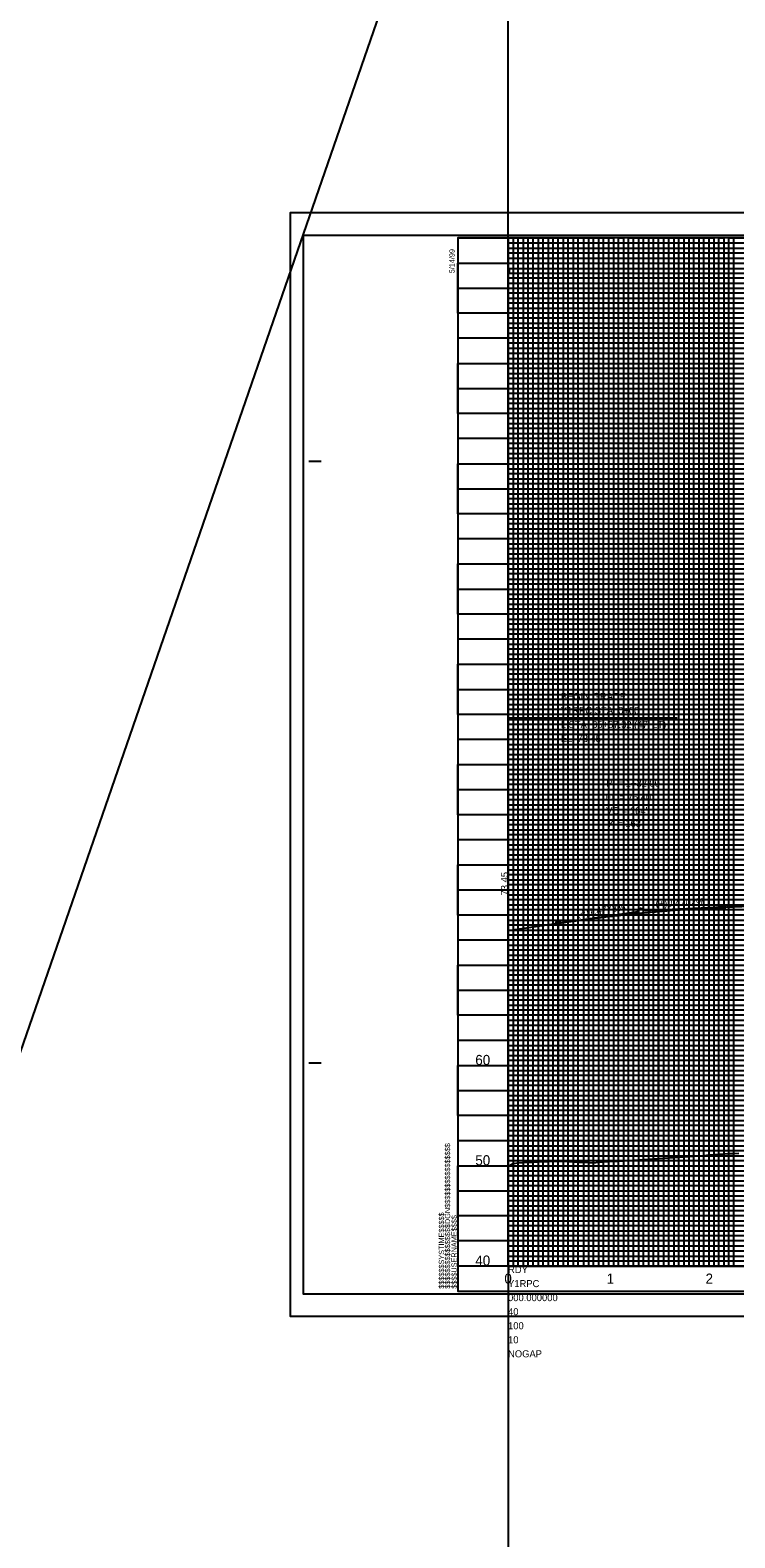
# Model space of a CAD drawing. Extents: x 2345490 to 2445302, y 465165 to 573888.
# Drawn here: x 2410419 to 2411121, y 508449 to 509953 of the extents above; entities that cross this region are included whole.
import ezdxf

# ---------------------------------------------------------------- set-up
doc = ezdxf.new("R2010")
doc.units = 0
for name, color, linetype in [('Old_Level_1', 7, 'Continuous'), ('Old_Level_18', 7, 'Continuous'), ('Old_Level_2', 7, 'Continuous'), ('Old_Level_40', 7, 'Continuous'), ('Old_Level_41', 7, 'Continuous'), ('Old_Level_42', 7, 'Continuous'), ('Old_Level_43', 7, 'Continuous'), ('Old_Level_50', 7, 'Continuous'), ('Old_Level_51', 7, 'Continuous'), ('Old_Level_52', 7, 'Continuous'), ('Old_Level_63', 7, 'Continuous')]:
    doc.layers.add(name, color=color, linetype=linetype)

msp = doc.modelspace()

# ---------------------------------------------------------------- linework, layer by layer
at = {"layer": 'Old_Level_1'}
msp.add_lwpolyline([(2410895.325, 508819.65725), (2410900.325, 508822.7005), (2410905.325, 508823.16675), (2410910.325, 508823.63275), (2410915.325, 508823.853), (2410920.325, 508824.06825), (2410925.325, 508824.28325), (2410930.325, 508824.49775), (2410935.325, 508824.71225), (2410940.325, 508824.87375), (2410945.325, 508824.87125), (2410950.325, 508824.8685), (2410955.325, 508824.62775), (2410960.325, 508824.3675), (2410965.325, 508824.10725), (2410970.325, 508823.847), (2410975.325, 508823.5865), (2410980.325, 508823.483), (2410985.325, 508823.8715), (2410990.325, 508824.25975), (2410995.325, 508824.56), (2411000.325, 508824.831), (2411005.325, 508825.10225), (2411010.325, 508825.37375), (2411015.325, 508825.64525), (2411020.325, 508825.92725), (2411025.325, 508826.2425), (2411030.325, 508826.55775), (2411035.325, 508826.87925), (2411040.325, 508827.21125), (2411045.325, 508827.5435), (2411050.325, 508827.87575), (2411055.325, 508828.20825), (2411060.325, 508828.54275), (2411065.325, 508828.88375), (2411070.325, 508829.225), (2411075.325, 508829.56625), (2411080.325, 508829.94425), (2411085.325, 508830.3465), (2411090.325, 508830.7485), (2411095.325, 508831.15025), (2411100.325, 508831.53675), (2411105.325, 508831.8515), (2411110.325, 508832.16575), (2411115.325, 508832.4795), (2411120.325, 508832.793), (2411125.325, 508833.0915)], dxfattribs=at)
at = {"layer": 'Old_Level_18'}
msp.add_line((2410845.325, 508695.412), (2410845.325, 508695.412), dxfattribs=at)
msp.add_line((2410845.325, 508695.412), (2410845.325, 508695.412), dxfattribs=at)
msp.add_lwpolyline([(2412345.325, 509745.412), (2410845.325, 509745.412), (2410845.325, 508695.412), (2412345.325, 508695.412)], close=True, dxfattribs=at)
at = {"layer": 'Old_Level_2'}
for p, q in [((2406888.2485, 498751.813), (2414623.19775, 521117.51825)), ((2410895.325, 509266.712), (2410895.325, 509047.812)), ((2411063.7915, 509266.712), (2410895.325, 509266.712)), ((2411109.325, 509078.268), (2411030.072, 509074.54125)), ((2411109.325, 509078.268), (2411192.57825, 509082.183)), ((2410895.325, 509054.912), (2410945.325, 509062.2985)), ((2410945.325, 509062.2985), (2411024.60475, 509074.01025))]:
    msp.add_line(p, q, dxfattribs=at)
for centre, radius in [((2411027.325, 509074.412), 2.75), ((2411109.325, 509078.268), 2.25), ((2410945.325, 509062.2985), 2.25)]:
    msp.add_circle(centre, radius, dxfattribs=at)
for points in [[(2410945.325, 509062.2985), (2410948.605, 509062.77975), (2410951.885, 509063.25425), (2410955.165, 509063.7225), (2410958.445, 509064.18375), (2410961.725, 509064.63875), (2410965.005, 509065.08675), (2410968.285, 509065.5285), (2410971.565, 509065.9635), (2410974.845, 509066.39175), (2410978.125, 509066.81375), (2410981.405, 509067.22875), (2410984.685, 509067.6375), (2410987.965, 509068.03925), (2410991.245, 509068.43475), (2410994.525, 509068.8235), (2410997.805, 509069.20575), (2411001.085, 509069.58125), (2411004.365, 509069.95), (2411007.645, 509070.3125), (2411010.925, 509070.66825), (2411014.205, 509071.01725), (2411017.485, 509071.35975), (2411020.765, 509071.69575), (2411024.045, 509072.025), (2411027.325, 509072.34775), (2411030.605, 509072.66375), (2411033.885, 509072.97325), (2411037.165, 509073.27625), (2411040.445, 509073.5725), (2411043.725, 509073.862), (2411047.005, 509074.14525), (2411050.285, 509074.4215), (2411053.565, 509074.6915), (2411056.845, 509074.95475), (2411060.125, 509075.21125), (2411063.405, 509075.46125), (2411066.685, 509075.70475), (2411069.965, 509075.9415), (2411073.245, 509076.17175), (2411076.525, 509076.3955), (2411079.805, 509076.6125), (2411083.085, 509076.82275), (2411086.365, 509077.0265), (2411089.645, 509077.22375), (2411092.925, 509077.41425), (2411096.205, 509077.59825), (2411099.485, 509077.77575), (2411102.765, 509077.9465), (2411106.045, 509078.1105), (2411109.325, 509078.268)], [(2411109.325, 509078.268), (2411112.765, 509078.426), (2411116.205, 509078.576), (2411119.645, 509078.7185), (2411123.085, 509078.85325), (2411126.525, 509078.98), (2411129.965, 509079.09925), (2411133.405, 509079.2105), (2411136.845, 509079.31425), (2411140.285, 509079.41), (2411143.725, 509079.49825), (2411147.165, 509079.57875), (2411150.605, 509079.65125), (2411154.045, 509079.71625), (2411157.485, 509079.7735), (2411160.925, 509079.82275), (2411164.365, 509079.8645), (2411167.805, 509079.89825), (2411171.245, 509079.9245), (2411174.685, 509079.943), (2411178.125, 509079.9535), (2411181.565, 509079.9565), (2411185.005, 509079.95175), (2411188.445, 509079.939), (2411191.885, 509079.91875), (2411195.325, 509079.89075), (2411198.765, 509079.855), (2411202.205, 509079.81125), (2411205.645, 509079.76), (2411209.085, 509079.701), (2411212.525, 509079.634), (2411215.965, 509079.5595), (2411219.405, 509079.47725), (2411222.845, 509079.38725), (2411226.285, 509079.28925), (2411229.725, 509079.18375), (2411233.165, 509079.0705), (2411236.605, 509078.9495), (2411240.045, 509078.8205), (2411243.485, 509078.684), (2411246.925, 509078.53975), (2411250.365, 509078.38775), (2411253.805, 509078.228), (2411257.245, 509078.06025), (2411260.685, 509077.885), (2411264.125, 509077.702), (2411267.565, 509077.51125), (2411271.005, 509077.31275), (2411274.445, 509077.10625), (2411277.885, 509076.89225), (2411281.325, 509076.6705)]]:
    msp.add_spline(points, degree=3, dxfattribs=at)
at = {"layer": 'Old_Level_40'}
msp.add_line((2410845.325, 508695.412), (2410845.325, 508695.412), dxfattribs=at)
msp.add_line((2410845.325, 508695.412), (2410845.325, 508695.412), dxfattribs=at)
msp.add_line((2410845.325, 508695.412), (2410845.325, 508695.412), dxfattribs=at)
msp.add_line((2410845.325, 508695.412), (2410845.325, 508695.412), dxfattribs=at)
at = {"layer": 'Old_Level_41'}
for p, q in [((2410696.825, 509522.912), (2410709.325, 509522.912)), ((2410696.825, 508922.912), (2410709.325, 508922.912)), ((2412345.325, 508720.412), (2410845.325, 508720.412))]:
    msp.add_line(p, q, dxfattribs=at)
for points in [[(2410845.325, 509745.412), (2410895.325, 509745.412), (2410895.325, 508720.412), (2410945.325, 508720.412), (2410945.325, 509745.412), (2410995.325, 509745.412), (2410995.325, 508720.412), (2411045.325, 508720.412), (2411045.325, 509745.412), (2411095.325, 509745.412), (2411095.325, 508720.412), (2411145.325, 508720.412)], [(2410920.325, 508720.412), (2410920.325, 509745.412), (2410970.325, 509745.412), (2410970.325, 508720.412), (2411020.325, 508720.412), (2411020.325, 509745.412), (2411070.325, 509745.412), (2411070.325, 508720.412), (2411120.325, 508720.412), (2411120.325, 509745.412), (2411170.325, 509745.412)], [(2410845.325, 509695.412), (2412145.275, 509695.412)], [(2412145.275, 509645.412), (2410845.325, 509645.412), (2410845.325, 509595.362), (2412345.325, 509595.362)], [(2412345.325, 509570.412), (2410845.325, 509570.412), (2410845.325, 509620.412), (2412145.275, 509620.412)], [(2412345.325, 509545.412), (2410845.325, 509545.412), (2410845.325, 509495.412), (2412345.325, 509495.412)], [(2412345.325, 509470.412), (2410845.325, 509470.412), (2410845.325, 509520.412), (2412345.325, 509520.412)], [(2412345.325, 509445.412), (2410845.325, 509445.412), (2410845.325, 509395.412), (2412345.325, 509395.412)], [(2412345.325, 509345.412), (2410845.325, 509345.412), (2410845.325, 509295.412), (2412345.325, 509295.412)], [(2412345.325, 509245.412), (2410845.325, 509245.412), (2410845.325, 509195.412), (2412345.325, 509195.412)], [(2412345.325, 509145.412), (2410845.325, 509145.412), (2410845.325, 509095.412), (2412345.325, 509095.412)], [(2412345.325, 509070.412), (2410845.325, 509070.412), (2410845.325, 509120.412), (2412345.325, 509120.412)], [(2412345.325, 509045.412), (2410845.325, 509045.412), (2410845.325, 508995.412), (2412345.325, 508995.412)], [(2412345.325, 508970.412), (2410845.325, 508970.412), (2410845.325, 509020.412), (2412345.325, 509020.412)], [(2412345.325, 508945.412), (2410845.325, 508945.412), (2410845.325, 508895.412), (2412345.325, 508895.412)], [(2412345.325, 508845.412), (2410845.325, 508845.412), (2410845.325, 508795.412), (2412345.325, 508795.412)], [(2412345.325, 508770.412), (2410845.325, 508770.412), (2410845.325, 508820.412), (2412345.325, 508820.412)], [(2412345.325, 508745.412), (2410845.325, 508745.412)], [(2410882.825, 508695.412), (2410882.825, 508695.412)]]:
    msp.add_lwpolyline(points, dxfattribs=at)
at = {"layer": 'Old_Level_42'}
for points in [[(2412145.275, 509670.412), (2410845.425, 509670.412), (2410845.425, 509720.362), (2412145.275, 509720.362)], [(2412345.325, 509370.412), (2410845.325, 509370.412), (2410845.325, 509420.412), (2412345.325, 509420.412)], [(2412345.325, 509270.412), (2410845.325, 509270.412), (2410845.325, 509320.412), (2412345.325, 509320.412)], [(2412345.325, 509170.412), (2410845.325, 509170.412), (2410845.325, 509220.412), (2412345.325, 509220.412)], [(2412345.325, 508870.412), (2410845.325, 508870.412), (2410845.325, 508920.412), (2412345.325, 508920.412)]]:
    msp.add_lwpolyline(points, dxfattribs=at)
at = {"layer": 'Old_Level_43'}
for p, q in [((2412295.325, 509565.412), (2410895.325, 509565.412)), ((2410895.325, 509565.412), (2410895.325, 509560.412)), ((2410895.325, 509560.412), (2412295.325, 509560.412)), ((2412295.325, 509540.412), (2410895.325, 509540.412))]:
    msp.add_line(p, q, dxfattribs=at)
for points in [[(2410900.325, 509745.412), (2410905.325, 509745.412), (2410910.325, 509745.412), (2410915.325, 509745.412), (2410925.325, 509745.412), (2410892.275, 509745.412), (2410897.275, 509745.412), (2410855.325, 509745.412), (2410860.325, 509745.412), (2410865.325, 509745.412), (2410875.325, 509745.412), (2410880.325, 509745.412), (2410885.325, 509745.412), (2410890.325, 509745.412), (2410900.325, 509745.412), (2410900.325, 508720.412), (2410905.325, 508720.412), (2410905.325, 509745.412), (2410910.325, 509745.412), (2410910.325, 508720.412), (2410915.325, 508720.412), (2410915.325, 509745.412), (2410925.325, 509745.412), (2410925.325, 508720.412), (2410930.325, 508720.412), (2410930.325, 509745.412), (2410935.325, 509745.412), (2410935.325, 508720.412), (2410940.325, 508720.412), (2410940.325, 509745.412), (2410950.325, 509745.412), (2410950.325, 508720.412), (2410955.325, 508720.412), (2410955.325, 509745.412), (2410960.325, 509745.412), (2410960.325, 508720.412), (2410965.325, 508720.412), (2410965.325, 509745.412), (2410975.325, 509745.412), (2410975.325, 508720.412), (2410980.325, 508720.412), (2410980.325, 509745.412), (2410985.325, 509745.412), (2410985.325, 508720.412), (2410990.325, 508720.412), (2410990.325, 509745.412), (2411000.325, 509745.412), (2411000.325, 508720.412), (2411005.325, 508720.412), (2411005.325, 509745.412), (2411010.325, 509745.412), (2411010.325, 508720.412), (2411015.325, 508720.412), (2411015.325, 509745.412), (2411025.325, 509745.412), (2411025.325, 508720.412), (2411030.325, 508720.412), (2411030.325, 509745.412), (2411035.325, 509745.412), (2411035.325, 508720.412), (2411040.325, 508720.412), (2411040.325, 509745.412), (2411050.325, 509745.412), (2411050.325, 508720.412), (2411055.325, 508720.412), (2411055.325, 509745.412), (2411060.325, 509745.412), (2411060.325, 508720.412)], [(2412145.275, 509740.412), (2410895.325, 509740.412), (2410895.325, 509735.412), (2412145.275, 509735.412)], [(2411060.325, 508720.412), (2411065.325, 508720.412), (2411065.325, 509745.412), (2411075.325, 509745.412), (2411075.325, 508720.412), (2411080.325, 508720.412), (2411080.325, 509745.412), (2411085.325, 509745.412), (2411085.325, 508720.412), (2411090.325, 508720.412), (2411090.325, 509745.412), (2411100.325, 509745.412), (2411100.325, 508720.412), (2411105.325, 508720.412), (2411105.325, 509745.412), (2411105.325, 509745.412), (2411110.325, 509745.412), (2411110.325, 508720.412), (2411115.325, 508720.412), (2411115.325, 509745.412), (2411125.325, 509745.412)], [(2412145.275, 509730.412), (2410895.325, 509730.412), (2410895.325, 509725.412), (2412145.275, 509725.412)], [(2412145.275, 509714.662), (2410896.325, 509714.662), (2410896.325, 509710.412), (2412145.275, 509710.412)], [(2412145.275, 509705.412), (2410895.325, 509705.412), (2410895.325, 509700.412), (2412145.275, 509700.412)], [(2412145.275, 509690.412), (2410895.325, 509690.412), (2410895.325, 509685.412), (2412145.275, 509685.412)], [(2412145.275, 509680.412), (2410895.325, 509680.412), (2410895.325, 509675.412), (2412145.275, 509675.412)], [(2412145.275, 509665.412), (2410895.325, 509665.412), (2410895.325, 509660.412), (2412145.275, 509660.412)], [(2412145.275, 509655.412), (2410895.325, 509655.412), (2410895.325, 509650.412), (2412145.275, 509650.412)], [(2412145.275, 509640.412), (2410895.325, 509640.412), (2410895.325, 509635.412), (2412145.275, 509635.412)], [(2412145.275, 509630.412), (2410895.325, 509630.412), (2410895.325, 509625.412), (2412145.275, 509625.412)], [(2412145.275, 509615.412), (2410895.325, 509615.412), (2410895.325, 509610.412), (2412145.275, 509610.412)], [(2412295.325, 509605.412), (2410895.325, 509605.412), (2410895.325, 509605.412), (2410895.325, 509585.412), (2412295.325, 509585.412)], [(2410895.325, 509600.412), (2412295.325, 509600.412)], [(2412295.325, 509590.412), (2410895.325, 509590.412)], [(2412295.325, 509580.412), (2410895.325, 509580.412), (2410895.325, 509575.412), (2412295.325, 509575.412)], [(2412295.325, 509555.412), (2410895.325, 509555.412), (2410895.325, 509550.412), (2412295.325, 509550.412)], [(2412295.325, 509535.412), (2410895.325, 509535.412), (2410895.325, 509530.412), (2412295.325, 509530.412)], [(2412295.325, 509525.412), (2410895.325, 509525.412)], [(2410895.325, 509515.412), (2412295.325, 509515.412)], [(2412295.325, 509510.412), (2410895.325, 509510.412), (2410895.325, 509505.412), (2412295.325, 509505.412)], [(2412295.325, 509500.412), (2410895.325, 509500.412), (2410895.325, 509490.412), (2412295.325, 509490.412)], [(2412295.325, 509485.412), (2410895.325, 509485.412), (2410895.325, 509480.412), (2412295.325, 509480.412)], [(2412295.325, 509475.412), (2410895.325, 509475.412), (2410895.325, 509465.412), (2412295.325, 509465.412)], [(2412295.325, 509460.412), (2410895.325, 509460.412), (2410895.325, 509455.412), (2412295.325, 509455.412)], [(2412295.325, 509450.412), (2410895.325, 509450.412), (2410895.325, 509440.412), (2412295.325, 509440.412)], [(2412295.325, 509435.412), (2410895.325, 509435.412), (2410895.325, 509430.412), (2412295.325, 509430.412)], [(2412295.325, 509425.412), (2410895.325, 509425.412), (2410895.325, 509415.412), (2412295.325, 509415.412)], [(2412295.325, 509410.412), (2410895.325, 509410.412), (2410895.325, 509405.412), (2412295.325, 509405.412)], [(2412295.325, 509400.412), (2410895.325, 509400.412), (2410895.325, 509390.412), (2412295.325, 509390.412)], [(2412295.325, 509385.412), (2410895.325, 509385.412), (2410895.325, 509380.412), (2412295.325, 509380.412)], [(2412295.325, 509375.412), (2410895.325, 509375.412), (2410895.325, 509365.412), (2412295.325, 509365.412)], [(2412295.325, 509360.412), (2410895.325, 509360.412), (2410895.325, 509355.412), (2412295.325, 509355.412)], [(2412295.325, 509350.412), (2410895.325, 509350.412), (2410895.325, 509340.412), (2412295.325, 509340.412)], [(2412295.325, 509335.412), (2410895.325, 509335.412), (2410895.325, 509330.412), (2412295.325, 509330.412)], [(2412295.325, 509325.412), (2410895.325, 509325.412), (2410895.325, 509315.412), (2412295.325, 509315.412)], [(2412295.325, 509310.412), (2410895.325, 509310.412), (2410895.325, 509305.412), (2412295.325, 509305.412)], [(2412295.325, 509300.412), (2410895.325, 509300.412), (2410895.325, 509290.412), (2412295.325, 509290.412)], [(2412295.325, 509285.412), (2410895.325, 509285.412), (2410895.325, 509280.412), (2412295.325, 509280.412)], [(2412295.325, 509275.412), (2410895.325, 509275.412), (2410895.325, 509265.412), (2412295.325, 509265.412)], [(2412295.325, 509260.412), (2410895.325, 509260.412), (2410895.325, 509255.412), (2412295.325, 509255.412)], [(2412295.325, 509250.412), (2410895.325, 509250.412), (2410895.325, 509240.412), (2412295.325, 509240.412)], [(2412295.325, 509235.412), (2410895.325, 509235.412), (2410895.325, 509230.412), (2412295.325, 509230.412)], [(2412295.325, 509225.412), (2410895.325, 509225.412)], [(2410895.325, 509215.412), (2412295.325, 509215.412)], [(2412295.325, 509210.412), (2410895.325, 509210.412), (2410895.325, 509205.412), (2412295.325, 509205.412)], [(2412295.325, 509200.412), (2410895.325, 509200.412), (2410895.325, 509190.412), (2412295.325, 509190.412)], [(2412295.325, 509185.412), (2410895.325, 509185.412), (2410895.325, 509180.412), (2412295.325, 509180.412)], [(2412295.325, 509175.412), (2410895.325, 509175.412), (2410895.325, 509165.412), (2412295.325, 509165.412)], [(2412295.325, 509160.412), (2410895.325, 509160.412), (2410895.325, 509155.412), (2412295.325, 509155.412)], [(2412295.325, 509150.412), (2410895.325, 509150.412), (2410895.325, 509140.412), (2412295.325, 509140.412)], [(2412295.325, 509135.412), (2410895.325, 509135.412), (2410895.325, 509130.412), (2412295.325, 509130.412)], [(2412295.325, 509125.412), (2410895.325, 509125.412), (2410895.325, 509115.412), (2412295.325, 509115.412)], [(2412295.325, 509110.412), (2410895.325, 509110.412), (2410895.325, 509105.412), (2412295.325, 509105.412)], [(2412295.325, 509100.412), (2410895.325, 509100.412), (2410895.325, 509090.412), (2412295.325, 509090.412)], [(2412295.325, 509085.412), (2410895.325, 509085.412), (2410895.325, 509080.412), (2412295.325, 509080.412)], [(2412295.325, 509075.412), (2410895.325, 509075.412), (2410895.325, 509065.412), (2412295.325, 509065.412)], [(2412295.325, 509060.412), (2410895.325, 509060.412), (2410895.325, 509055.412), (2412295.325, 509055.412)], [(2412295.325, 509050.412), (2410895.325, 509050.412), (2410895.325, 509040.412), (2412295.325, 509040.412)], [(2412295.325, 509035.412), (2410895.325, 509035.412), (2410895.325, 509030.412), (2412295.325, 509030.412)], [(2412295.325, 509025.412), (2410895.325, 509025.412), (2410895.325, 509015.412), (2412295.325, 509015.412)], [(2412295.325, 509010.412), (2410895.325, 509010.412), (2410895.325, 509005.412), (2412295.325, 509005.412)], [(2412295.325, 509000.412), (2410895.325, 509000.412), (2410895.325, 508990.412), (2412295.325, 508990.412)], [(2412295.325, 508985.412), (2410895.325, 508985.412), (2410895.325, 508980.412), (2412295.325, 508980.412)], [(2412295.325, 508975.412), (2410895.325, 508975.412), (2410895.325, 508965.412), (2412295.325, 508965.412)], [(2412295.325, 508960.412), (2410895.325, 508960.412), (2410895.325, 508955.412), (2412295.325, 508955.412)], [(2412295.325, 508950.412), (2410895.325, 508950.412), (2410895.325, 508940.412), (2412295.325, 508940.412)], [(2412295.325, 508935.412), (2410895.325, 508935.412), (2410895.325, 508930.412), (2412295.325, 508930.412)], [(2412295.325, 508925.412), (2410895.325, 508925.412)], [(2410895.325, 508915.412), (2412295.325, 508915.412)], [(2412295.325, 508910.412), (2410895.325, 508910.412), (2410895.325, 508905.412), (2412295.325, 508905.412)], [(2412295.325, 508900.412), (2410895.325, 508900.412)], [(2410895.325, 508890.412), (2412295.325, 508890.412)], [(2412295.325, 508885.412), (2410895.325, 508885.412), (2410895.325, 508880.412), (2412295.325, 508880.412)], [(2412295.325, 508875.412), (2410895.325, 508875.412), (2410895.325, 508865.412), (2412295.325, 508865.412)], [(2412295.325, 508860.412), (2410895.325, 508860.412), (2410895.325, 508855.412), (2412295.325, 508855.412)], [(2412295.325, 508850.412), (2410895.325, 508850.412), (2410895.325, 508840.412), (2412295.325, 508840.412)], [(2412295.325, 508835.412), (2410895.325, 508835.412), (2410895.325, 508830.412), (2412295.325, 508830.412)], [(2412295.325, 508825.412), (2410895.325, 508825.412), (2410895.325, 508815.412), (2412295.325, 508815.412)], [(2412295.325, 508810.412), (2410895.325, 508810.412), (2410895.325, 508805.412), (2412295.325, 508805.412)], [(2412295.325, 508800.412), (2410895.325, 508800.412), (2410895.325, 508790.412), (2412295.325, 508790.412)], [(2412295.325, 508785.412), (2410895.325, 508785.412), (2410895.325, 508780.412), (2412295.325, 508780.412)], [(2412295.325, 508775.412), (2410895.325, 508775.412), (2410895.325, 508765.412), (2412295.325, 508765.412)], [(2412295.325, 508760.412), (2410895.325, 508760.412), (2410895.325, 508755.412), (2412295.325, 508755.412)], [(2412295.325, 508750.412), (2410895.325, 508750.412), (2410895.325, 508740.412), (2412295.325, 508740.412)], [(2412295.325, 508735.412), (2410895.325, 508735.412), (2410895.325, 508730.412), (2412295.325, 508730.412)], [(2412295.325, 508725.412), (2410895.325, 508725.412)]]:
    msp.add_lwpolyline(points, dxfattribs=at)
at = {"layer": 'Old_Level_50'}
msp.add_line((2410678.325, 508670.412), (2410678.325, 508670.412), dxfattribs=at)
msp.add_lwpolyline([(2412357.825, 509747.962), (2410691.325, 509747.962), (2410691.325, 508692.862), (2412357.825, 508692.862)], close=True, dxfattribs=at)
at = {"layer": 'Old_Level_51'}
msp.add_lwpolyline([(2412362.325, 509770.412), (2410678.325, 509770.412), (2410678.325, 508670.412), (2412362.325, 508670.412)], close=True, dxfattribs=at)
at = {"layer": 'Old_Level_52'}
msp.add_line((2410691.325, 508692.862), (2410691.325, 508692.862), dxfattribs=at)
at = {"layer": 'Old_Level_63'}
for p, q in [((2410895.325, 508720.412), (2410895.325, 511220.412)), ((2411095.325, 509078.362), (2411095.325, 509215.97775)), ((2411095.325, 509075.832), (2411095.325, 508889.67675)), ((2410945.325, 509062.292), (2410945.325, 508889.67675)), ((2410995.325, 509068.912), (2410995.325, 508889.67675)), ((2411045.325, 509073.992), (2411045.325, 508889.67675)), ((2410895.325, 509054.952), (2410895.325, 508889.67675)), ((2410895.325, 508720.412), (2412278.50525, 508720.412)), ((2410895.325, 508720.412), (2410895.325, 506220.412))]:
    msp.add_line(p, q, dxfattribs=at)

# ---------------------------------------------------------------- texts
at = {"layer": 'Old_Level_1'}
for s, height, p in [('60', 10.000001, (2410862.7115, 508920.912)), ('50', 10.000001, (2410862.7115, 508820.912)), ('40', 10.000001, (2410862.7115, 508720.912)), ('0', 10, (2410891.666, 508702.912)), ('1', 10, (2410993.5055, 508702.912)), ('2', 10, (2411092.054, 508702.912))]:
    msp.add_text(s, height=height, dxfattribs=at).set_placement(p)
at = {"layer": 'Old_Level_2'}
for s, height, p in [('BEGIN GRADE', 7.0000005, (2410947.8335, 509284.85525)), ('Y1RPC STA. 0+00', 7.0000005, (2410947.8335, 509270.85525)), ("L STA. 35+67.32 (47' LT)", 7.0000005, (2410947.8335, 509256.85525)), ('EL. 73.45', 7.000001, (2410947.8335, 509242.85525)), ('PI = 1+32.00', 7.0000005, (2410992.99625, 509198.36875)), ("EL = 75.40'", 7.0000005, (2410992.325, 509184.412)), ("VC = 164'", 7.000001, (2410993.02475, 509170.98425)), ('K = 163', 7.000001, (2410995.232, 509158.22175))]:
    msp.add_text(s, height=height, dxfattribs=at).set_placement(p)
for s, rotation, p in [('73.45', 90, (2410895.325, 509089.912)), ('(+)1.4773%', 8.40337222, (2410964.528, 509068.168)), ('(+)0.4702%', 2.69228333, (2411042.368, 509078.12275))]:
    msp.add_text(s, height=7.000001, rotation=rotation, dxfattribs=at).set_placement(p)
at = {"layer": 'Old_Level_41'}
for s, p in [('5/14/99', (2410842.075, 509710.212)), ('$$$$$$$$$$$$$$$$DGN$$$$$$$$$$$$$$$$', (2410837.675, 508697.7745)), ('$$$$$$SYSTIME$$$$$', (2410831.625, 508697.7745)), ('$$$$USERNAME$$$$', (2410844.25, 508697.787))]:
    msp.add_text(s, height=5.25, rotation=90, dxfattribs=at).set_placement(p)
at = {"layer": 'Old_Level_63'}
for s, p in [('RDY', (2410895.325, 508713.412)), ('Y1RPC', (2410895.325, 508699.412)), ('000.000000', (2410895.325, 508685.412)), ('40', (2410895.325, 508671.412)), ('100', (2410895.325, 508657.412)), ('10', (2410895.325, 508643.412)), ('NOGAP', (2410895.325, 508629.412))]:
    msp.add_text(s, height=7.000001, dxfattribs=at).set_placement(p)

doc.saveas('drawing.dxf')
